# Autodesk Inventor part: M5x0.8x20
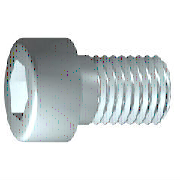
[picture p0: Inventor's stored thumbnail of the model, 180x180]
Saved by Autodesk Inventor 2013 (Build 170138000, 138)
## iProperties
IsCustomPart: 0
Created: 2009-02
Part Number: M5x0.8x20
Material: Steel, Mild
Description: 6각머리 태핑 나사
Document SubType Name: Modeling
Standard: KS B 1003
Designer: KYOUNG IL JANG
Standards Organization: KS
Language: ko-KR
Size Designation: M 5 x 20
Categories: <MemberInstance><Categories><Category DisplayName="조임쇠" InternalName="e4da775c-781d-43d5-af7c-5136215cf5a6" Mnemonic="FSTN"><Category DisplayName="볼트" InternalN
Density: 1 g/cm^3
Author: KYOUNG IL JANG
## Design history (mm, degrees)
sketch "스케치1"
  geometry: L1 (-1.167, 0)-(20, 0); L2 (20, 0)-(20, 2.5); L3 (20, 2.5)-(2, 2.5); L4 (2, 2.5)-(1.509, 2.5); L5 (1.509, 2.5)-(0, 2.5); L6 (0, 2.5)-(0, 4.25); L7 (0, 4.25)-(-5, 4.25); L8 (-5, 4.25)-(-5, 2.309); L9 (-5, 2.309)-(-2.5, 2.309); L10 (-2.5, 2.309)-(-1.167, 0); L11 (-10, 0)-(25, 0) reference; L12 (0, -0.85)-(0, 5.1) reference; L13 (2, 2.5)-(0, 2.5)
  constraints: 22 end point, 6 parallel, 2 collinear, 2 perpendicular, 1 horizontal, 1 point on line
  dimensions: "d1" = 18 distance from line of L3.end L2 (= GEL); "d2" = 0.49086 distance of L4.end L3.end (computed from GAL); "d3" = 5 distance between parallel lines of L8 L6 (= KOH); "d4" = 2.5 distance of L8.end L9.end (= INTI); "d5" = 60 deg angle of L10 L1; "d6" = 5 diameter of L3 L1 (= GD); "d7" = 5 diameter of L5 L1 (= BDM); "d8" = 4.6188 diameter of L9 L1 (= 1.1547 x SW); "d9" = 8.5 diameter of L7 L1 (= KOD); "d26" = 20 distance between parallel lines of L12 L2 (= NLG)
revolve "본체" sketch "스케치1" stored, may be unused: angle "d10" = 90 deg
sketch "스케치2"
  geometry: L1 (0, -5.95)-(0, 5.95) reference; L2 (-5.95, 0)-(5.95, 0) reference; L3 (2.309, 0)-(1.155, -2); L4 (1.155, -2)-(-1.155, -2); L5 (-1.155, -2)-(-2.309, 0); L6 (-2.309, 0)-(-1.155, 2); L7 (-1.155, 2)-(1.155, 2); L8 (1.155, 2)-(2.309, 0); 2 further points
  constraints: 12 end point, 1 coincident, 1 horizontal alignment, 1 point on line, 12 other
extrude "슬롯" join sketch "스케치2" stored distance "d11" = 10; taper "d12" = 0 deg
workplane "Work Plane1"
fillet "Fillet2" dims "d30" = 0.1 (= R)
body "Solid1"
fillet "모깎기1" dims "d17" = 0.5 (= RR)
feature "스레드" dims "d13" = 18 (= GEL), "d14" = 0
chamfer "모따기1" distance "d15" = 0.49076 (= -0.5 x SPD + 0.5 x GD); stored, may be unused: second distance "d16" = 0.49076 (= GUL), angle "d27" = 45 deg
other parameters: "GD" = 5 (= NND) [user parameter; used in 2 equation terms], "NLG" = 20 [user parameter; used in 1 equation term], "GEL" = 18 [user parameter; used in 2 equation terms], "KOD" = 8.5 [user parameter; used in 1 equation term], "KOH" = 5 [user parameter; used in 1 equation term], "INTI" = 2.5 [user parameter; used in 1 equation term], "GAL" = 0.49076 (= 0.61345 x PTC) [user parameter; used in 1 equation term], "GUL" = 0.49076 (= 0.61345 x PTC) [user parameter; used in 1 equation term], "BDM" = 5 (= NND) [user parameter; used in 1 equation term], "SW" = 4 [user parameter; used in 2 equation terms], "RR" = 0.5 [user parameter; used in 1 equation term], "SPD" = 4.01848 (= NND - 1.2269 x PTC) [user parameter; used in 1 equation term], "d19" = 0, "d28" = 0, "d29" = 0, "R" = 0.1 [user parameter; used in 1 equation term], "PHH" = 0.2 [user parameter], "GD1" = 4.01848 (= THREADDIA - 1.2269 x PTC) [user parameter], "THREADDIA" = 5 [user parameter; used in 1 equation term], "FAWI" = 45 deg [user parameter], "TPU" = 12.5 (computed from PTC) [user parameter], "PTC" = 0.8 [user parameter; used in 5 equation terms], "NND" = 5 [user parameter; used in 3 equation terms], "TOA" = 30 deg [user parameter], "E0" = 4.62 (= 1.155 x SW) [user parameter]
